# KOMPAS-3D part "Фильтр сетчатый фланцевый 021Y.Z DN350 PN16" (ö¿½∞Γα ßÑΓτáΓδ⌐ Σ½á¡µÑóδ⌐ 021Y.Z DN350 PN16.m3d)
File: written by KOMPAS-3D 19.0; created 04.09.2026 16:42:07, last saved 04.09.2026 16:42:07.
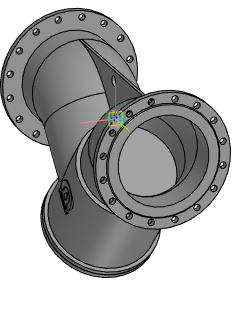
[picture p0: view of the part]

Document properties: Автор: Энергия; Полное имя файла: Z:\3.Личные\sachek\Dendor\_3D для проектировщиков\8.1 Фильтр сетчатый 021Y.Z\021Y.Z_STP\Фильтр сетчатый фланцевый 021Y.Z DN350 PN16.m3d

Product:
- Part/product: Фильтр сетчатый фланцевый 021Y.Z DN350 PN16

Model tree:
1. Операция без истории:1  (labels: Фильтр сетчатый фланцевый 021Y.Z DN350 PN16)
